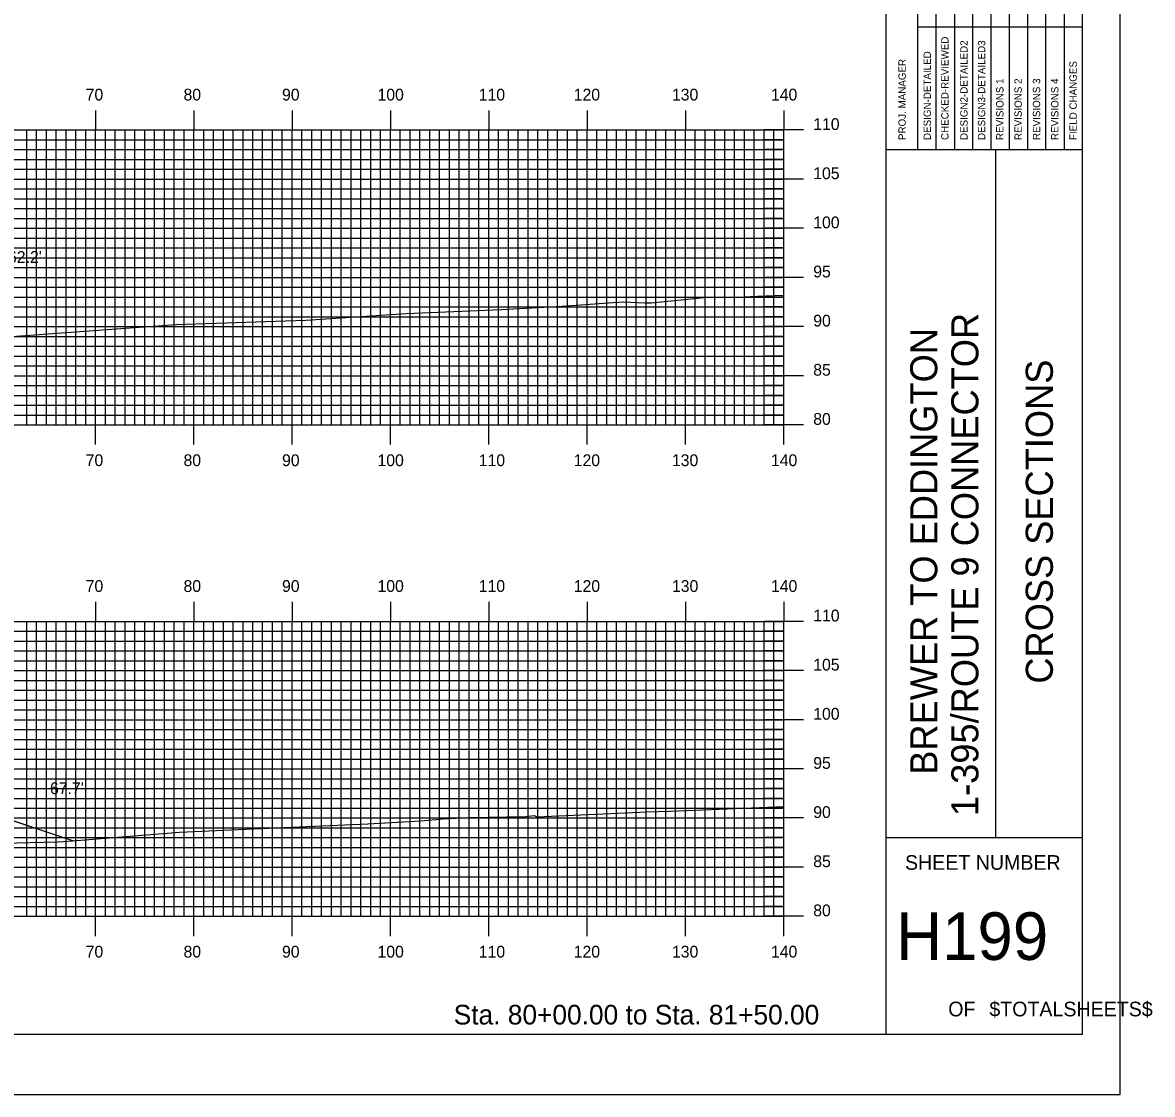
# Model space of a CAD drawing. Extents: x 1762578 to 1762921, y 442591 to 442811.
# Drawn here: x 1762806.4 to 1762921.3, y 442590.5 to 442699.6 of the extents above; entities that cross this region are included whole.
import ezdxf

# ---------------------------------------------------------------- set-up
doc = ezdxf.new("R2010")
doc.units = 0
for name, color, linetype in [('BORDER', 7, 'Continuous'), ('D_Roadway_Centerline', 7, 'Continuous'), ('D_Roadway_SlopeLines', 7, 'Continuous'), ('D_Text_Standard', 7, 'Continuous'), ('H_V ANNOTATION', 7, 'Continuous'), ('MAJOR', 7, 'Continuous'), ('MINOR', 7, 'Continuous'), ('PLOT BOUNDARY', 7, 'Continuous'), ('S_Roadway_Centerline', 7, 'Continuous')]:
    doc.layers.add(name, color=color, linetype=linetype)

msp = doc.modelspace()

# ---------------------------------------------------------------- linework, layer by layer
at = {"layer": 'BORDER'}
for p, q in [((1762894.18, 442596.67), (1762894.18, 442806.67)), ((1762894.18, 442686.67), (1762914.18, 442686.67)), ((1762905.36, 442616.67), (1762905.36, 442686.67)), ((1762894.18, 442616.67), (1762914.18, 442616.67))]:
    msp.add_line(p, q, dxfattribs=at)
msp.add_lwpolyline([(1762594.18, 442596.67), (1762914.18, 442596.67), (1762914.18, 442806.67), (1762594.18, 442806.67)], close=True, dxfattribs=at)
for points in [[(1762899.27, 442686.68), (1762899.27, 442721.67)], [(1762901.14, 442721.67), (1762901.14, 442686.68)], [(1762903, 442686.68), (1762903, 442721.67)], [(1762904.86, 442686.68), (1762904.86, 442721.67)], [(1762906.73, 442686.68), (1762906.73, 442721.67)], [(1762908.59, 442686.68), (1762908.59, 442721.67)], [(1762910.45, 442686.68), (1762910.45, 442721.67)], [(1762912.32, 442686.68), (1762912.32, 442721.67)], [(1762897.41, 442686.68), (1762897.41, 442720.26)], [(1762897.41, 442699.17), (1762914.18, 442699.17)]]:
    msp.add_lwpolyline(points, dxfattribs=at)
at = {"layer": 'D_Roadway_Centerline'}
msp.add_lwpolyline([(1762668.07, 442614.67), (1762668.08, 442614.67), (1762705.54, 442627.15), (1762706.12, 442627.3), (1762706.12, 442627.3), (1762717.54, 442630.15), (1762717.54, 442630.15), (1762726.98, 442630.53), (1762731.78, 442630.72), (1762731.78, 442630.72), (1762738.78, 442630.98), (1762743.78, 442631.16), (1762743.78, 442631.16), (1762750.76, 442631.41), (1762755.78, 442631.59), (1762755.78, 442631.59), (1762763.78, 442631.27), (1762773.95, 442628.72), (1762773.95, 442628.72), (1762774.91, 442628.48), (1762775.78, 442628.27), (1762802.49, 442619.36), (1762811.53, 442616.35)], dxfattribs=at)
at = {"layer": 'D_Roadway_SlopeLines'}
msp.add_lwpolyline([(1762763.78, 442631.27), (1762775.78, 442628.27), (1762811.53, 442616.35)], dxfattribs=at)
at = {"layer": 'MAJOR'}
for p, q in [((1762813.78, 442690.67), (1762813.78, 442688.67)), ((1762823.78, 442690.67), (1762823.78, 442688.67)), ((1762833.78, 442690.67), (1762833.78, 442688.67)), ((1762843.78, 442690.67), (1762843.78, 442688.67)), ((1762853.78, 442690.67), (1762853.78, 442688.67)), ((1762863.78, 442690.67), (1762863.78, 442688.67)), ((1762873.78, 442690.67), (1762873.78, 442688.67)), ((1762883.78, 442690.67), (1762883.78, 442688.67)), ((1762603.78, 442688.67), (1762883.78, 442688.67)), ((1762603.78, 442688.67), (1762883.78, 442688.67)), ((1762813.78, 442658.67), (1762813.78, 442688.67)), ((1762823.78, 442658.67), (1762823.78, 442688.67)), ((1762833.78, 442658.67), (1762833.78, 442688.67)), ((1762843.78, 442658.67), (1762843.78, 442688.67)), ((1762853.78, 442658.67), (1762853.78, 442688.67)), ((1762863.78, 442658.67), (1762863.78, 442688.67)), ((1762873.78, 442658.67), (1762873.78, 442688.67)), ((1762885.78, 442688.67), (1762881.78, 442688.67)), ((1762883.78, 442658.67), (1762883.78, 442688.67)), ((1762883.78, 442658.67), (1762883.78, 442688.67)), ((1762603.78, 442683.67), (1762883.78, 442683.67)), ((1762885.78, 442683.67), (1762881.78, 442683.67)), ((1762603.78, 442678.67), (1762883.78, 442678.67)), ((1762885.78, 442678.67), (1762881.78, 442678.67)), ((1762603.78, 442673.67), (1762883.78, 442673.67)), ((1762885.78, 442673.67), (1762881.78, 442673.67)), ((1762603.78, 442668.67), (1762883.78, 442668.67)), ((1762885.78, 442668.67), (1762881.78, 442668.67)), ((1762603.78, 442663.67), (1762883.78, 442663.67)), ((1762885.78, 442663.67), (1762881.78, 442663.67)), ((1762603.78, 442658.67), (1762883.78, 442658.67)), ((1762603.78, 442658.67), (1762883.78, 442658.67)), ((1762813.78, 442656.66), (1762813.78, 442658.67)), ((1762823.78, 442656.66), (1762823.78, 442658.67)), ((1762833.78, 442656.66), (1762833.78, 442658.67)), ((1762843.78, 442656.66), (1762843.78, 442658.67)), ((1762853.78, 442656.66), (1762853.78, 442658.67)), ((1762863.78, 442656.66), (1762863.78, 442658.67)), ((1762873.78, 442656.66), (1762873.78, 442658.67)), ((1762885.78, 442658.67), (1762881.78, 442658.67)), ((1762883.78, 442656.66), (1762883.78, 442658.67)), ((1762813.78, 442640.67), (1762813.78, 442638.67)), ((1762823.78, 442640.67), (1762823.78, 442638.67)), ((1762833.78, 442640.67), (1762833.78, 442638.67)), ((1762843.78, 442640.67), (1762843.78, 442638.67)), ((1762853.78, 442640.67), (1762853.78, 442638.67)), ((1762863.78, 442640.67), (1762863.78, 442638.67)), ((1762873.78, 442640.67), (1762873.78, 442638.67)), ((1762883.78, 442640.67), (1762883.78, 442638.67)), ((1762603.78, 442638.67), (1762883.78, 442638.67)), ((1762603.78, 442638.67), (1762883.78, 442638.67)), ((1762813.78, 442608.67), (1762813.78, 442638.67)), ((1762823.78, 442608.67), (1762823.78, 442638.67)), ((1762833.78, 442608.67), (1762833.78, 442638.67)), ((1762843.78, 442608.67), (1762843.78, 442638.67)), ((1762853.78, 442608.67), (1762853.78, 442638.67)), ((1762863.78, 442608.67), (1762863.78, 442638.67)), ((1762873.78, 442608.67), (1762873.78, 442638.67)), ((1762885.78, 442638.67), (1762881.78, 442638.67)), ((1762883.78, 442608.67), (1762883.78, 442638.67)), ((1762883.78, 442608.67), (1762883.78, 442638.67)), ((1762603.78, 442633.67), (1762883.78, 442633.67)), ((1762885.78, 442633.67), (1762881.78, 442633.67)), ((1762603.78, 442628.67), (1762883.78, 442628.67)), ((1762885.78, 442628.67), (1762881.78, 442628.67)), ((1762603.78, 442623.67), (1762883.78, 442623.67)), ((1762885.78, 442623.67), (1762881.78, 442623.67)), ((1762603.78, 442618.67), (1762883.78, 442618.67)), ((1762885.78, 442618.67), (1762881.78, 442618.67)), ((1762603.78, 442613.67), (1762883.78, 442613.67)), ((1762885.78, 442613.67), (1762881.78, 442613.67)), ((1762603.78, 442608.67), (1762883.78, 442608.67)), ((1762603.78, 442608.67), (1762883.78, 442608.67)), ((1762813.78, 442606.66), (1762813.78, 442608.67)), ((1762823.78, 442606.66), (1762823.78, 442608.67)), ((1762833.78, 442606.66), (1762833.78, 442608.67)), ((1762843.78, 442606.66), (1762843.78, 442608.67)), ((1762853.78, 442606.66), (1762853.78, 442608.67)), ((1762863.78, 442606.66), (1762863.78, 442608.67)), ((1762873.78, 442606.66), (1762873.78, 442608.67)), ((1762885.78, 442608.67), (1762881.78, 442608.67)), ((1762883.78, 442606.66), (1762883.78, 442608.67))]:
    msp.add_line(p, q, dxfattribs=at)
at = {"layer": 'MINOR'}
for p, q in [((1762806.78, 442658.67), (1762806.78, 442688.67)), ((1762807.78, 442658.67), (1762807.78, 442688.67)), ((1762808.78, 442658.67), (1762808.78, 442688.67)), ((1762809.78, 442658.67), (1762809.78, 442688.67)), ((1762810.78, 442658.67), (1762810.78, 442688.67)), ((1762811.78, 442658.67), (1762811.78, 442688.67)), ((1762812.78, 442658.67), (1762812.78, 442688.67)), ((1762814.78, 442658.67), (1762814.78, 442688.67)), ((1762815.78, 442658.67), (1762815.78, 442688.67)), ((1762816.78, 442658.67), (1762816.78, 442688.67)), ((1762817.78, 442658.67), (1762817.78, 442688.67)), ((1762818.78, 442658.67), (1762818.78, 442688.67)), ((1762819.78, 442658.67), (1762819.78, 442688.67)), ((1762820.78, 442658.67), (1762820.78, 442688.67)), ((1762821.78, 442658.67), (1762821.78, 442688.67)), ((1762822.78, 442658.67), (1762822.78, 442688.67)), ((1762824.78, 442658.67), (1762824.78, 442688.67)), ((1762825.78, 442658.67), (1762825.78, 442688.67)), ((1762826.78, 442658.67), (1762826.78, 442688.67)), ((1762827.78, 442658.67), (1762827.78, 442688.67)), ((1762828.78, 442658.67), (1762828.78, 442688.67)), ((1762829.78, 442658.67), (1762829.78, 442688.67)), ((1762830.78, 442658.67), (1762830.78, 442688.67)), ((1762831.78, 442658.67), (1762831.78, 442688.67)), ((1762832.78, 442658.67), (1762832.78, 442688.67)), ((1762834.78, 442658.67), (1762834.78, 442688.67)), ((1762835.78, 442658.67), (1762835.78, 442688.67)), ((1762836.78, 442658.67), (1762836.78, 442688.67)), ((1762837.78, 442658.67), (1762837.78, 442688.67)), ((1762838.78, 442658.67), (1762838.78, 442688.67)), ((1762839.78, 442658.67), (1762839.78, 442688.67)), ((1762840.78, 442658.67), (1762840.78, 442688.67)), ((1762841.78, 442658.67), (1762841.78, 442688.67)), ((1762842.78, 442658.67), (1762842.78, 442688.67)), ((1762844.78, 442658.67), (1762844.78, 442688.67)), ((1762845.78, 442658.67), (1762845.78, 442688.67)), ((1762846.78, 442658.67), (1762846.78, 442688.67)), ((1762847.78, 442658.67), (1762847.78, 442688.67)), ((1762848.78, 442658.67), (1762848.78, 442688.67)), ((1762849.78, 442658.67), (1762849.78, 442688.67)), ((1762850.78, 442658.67), (1762850.78, 442688.67)), ((1762851.78, 442658.67), (1762851.78, 442688.67)), ((1762852.78, 442658.67), (1762852.78, 442688.67)), ((1762854.78, 442658.67), (1762854.78, 442688.67)), ((1762855.78, 442658.67), (1762855.78, 442688.67)), ((1762856.78, 442658.67), (1762856.78, 442688.67)), ((1762857.78, 442658.67), (1762857.78, 442688.67)), ((1762858.78, 442658.67), (1762858.78, 442688.67)), ((1762859.78, 442658.67), (1762859.78, 442688.67)), ((1762860.78, 442658.67), (1762860.78, 442688.67)), ((1762861.78, 442658.67), (1762861.78, 442688.67)), ((1762862.78, 442658.67), (1762862.78, 442688.67)), ((1762864.78, 442658.67), (1762864.78, 442688.67)), ((1762865.78, 442658.67), (1762865.78, 442688.67)), ((1762866.78, 442658.67), (1762866.78, 442688.67)), ((1762867.78, 442658.67), (1762867.78, 442688.67)), ((1762868.78, 442658.67), (1762868.78, 442688.67)), ((1762869.78, 442658.67), (1762869.78, 442688.67)), ((1762870.78, 442658.67), (1762870.78, 442688.67)), ((1762871.78, 442658.67), (1762871.78, 442688.67)), ((1762872.78, 442658.67), (1762872.78, 442688.67)), ((1762874.78, 442658.67), (1762874.78, 442688.67)), ((1762875.78, 442658.67), (1762875.78, 442688.67)), ((1762876.78, 442658.67), (1762876.78, 442688.67)), ((1762877.78, 442658.67), (1762877.78, 442688.67)), ((1762878.78, 442658.67), (1762878.78, 442688.67)), ((1762879.78, 442658.67), (1762879.78, 442688.67)), ((1762880.78, 442658.67), (1762880.78, 442688.67)), ((1762881.78, 442658.67), (1762881.78, 442688.67)), ((1762882.78, 442658.67), (1762882.78, 442688.67)), ((1762603.78, 442687.67), (1762883.78, 442687.67)), ((1762883.78, 442687.67), (1762881.78, 442687.67)), ((1762603.78, 442686.67), (1762883.78, 442686.67)), ((1762883.78, 442686.67), (1762881.78, 442686.67)), ((1762603.78, 442685.67), (1762883.78, 442685.67)), ((1762883.78, 442685.67), (1762881.78, 442685.67)), ((1762603.78, 442684.67), (1762883.78, 442684.67)), ((1762883.78, 442684.67), (1762881.78, 442684.67)), ((1762603.78, 442682.67), (1762883.78, 442682.67)), ((1762883.78, 442682.67), (1762881.78, 442682.67)), ((1762603.78, 442681.67), (1762883.78, 442681.67)), ((1762883.78, 442681.67), (1762881.78, 442681.67)), ((1762603.78, 442680.67), (1762883.78, 442680.67)), ((1762883.78, 442680.67), (1762881.78, 442680.67)), ((1762603.78, 442679.67), (1762883.78, 442679.67)), ((1762883.78, 442679.67), (1762881.78, 442679.67)), ((1762603.78, 442677.67), (1762883.78, 442677.67)), ((1762883.78, 442677.67), (1762881.78, 442677.67)), ((1762603.78, 442676.67), (1762883.78, 442676.67)), ((1762883.78, 442676.67), (1762881.78, 442676.67)), ((1762603.78, 442675.67), (1762883.78, 442675.67)), ((1762603.78, 442674.67), (1762883.78, 442674.67)), ((1762883.78, 442675.67), (1762881.78, 442675.67)), ((1762883.78, 442674.67), (1762881.78, 442674.67)), ((1762603.78, 442672.67), (1762883.78, 442672.67)), ((1762883.78, 442672.67), (1762881.78, 442672.67)), ((1762603.78, 442671.67), (1762883.78, 442671.67)), ((1762883.78, 442671.67), (1762881.78, 442671.67)), ((1762603.78, 442670.67), (1762883.78, 442670.67)), ((1762883.78, 442670.67), (1762881.78, 442670.67)), ((1762603.78, 442669.67), (1762883.78, 442669.67)), ((1762883.78, 442669.67), (1762881.78, 442669.67)), ((1762603.78, 442667.67), (1762883.78, 442667.67)), ((1762603.78, 442666.67), (1762883.78, 442666.67)), ((1762883.78, 442667.67), (1762881.78, 442667.67)), ((1762883.78, 442666.67), (1762881.78, 442666.67)), ((1762603.78, 442665.67), (1762883.78, 442665.67)), ((1762883.78, 442665.67), (1762881.78, 442665.67)), ((1762603.78, 442664.67), (1762883.78, 442664.67)), ((1762883.78, 442664.67), (1762881.78, 442664.67)), ((1762603.78, 442662.67), (1762883.78, 442662.67)), ((1762883.78, 442662.67), (1762881.78, 442662.67)), ((1762603.78, 442661.67), (1762883.78, 442661.67)), ((1762883.78, 442661.67), (1762881.78, 442661.67)), ((1762603.78, 442660.67), (1762883.78, 442660.67)), ((1762603.78, 442659.67), (1762883.78, 442659.67)), ((1762883.78, 442660.67), (1762881.78, 442660.67)), ((1762883.78, 442659.67), (1762881.78, 442659.67)), ((1762806.78, 442608.67), (1762806.78, 442638.67)), ((1762807.78, 442608.67), (1762807.78, 442638.67)), ((1762808.78, 442608.67), (1762808.78, 442638.67)), ((1762809.78, 442608.67), (1762809.78, 442638.67)), ((1762810.78, 442608.67), (1762810.78, 442638.67)), ((1762811.78, 442608.67), (1762811.78, 442638.67)), ((1762812.78, 442608.67), (1762812.78, 442638.67)), ((1762814.78, 442608.67), (1762814.78, 442638.67)), ((1762815.78, 442608.67), (1762815.78, 442638.67)), ((1762816.78, 442608.67), (1762816.78, 442638.67)), ((1762817.78, 442608.67), (1762817.78, 442638.67)), ((1762818.78, 442608.67), (1762818.78, 442638.67)), ((1762819.78, 442608.67), (1762819.78, 442638.67)), ((1762820.78, 442608.67), (1762820.78, 442638.67)), ((1762821.78, 442608.67), (1762821.78, 442638.67)), ((1762822.78, 442608.67), (1762822.78, 442638.67)), ((1762824.78, 442608.67), (1762824.78, 442638.67)), ((1762825.78, 442608.67), (1762825.78, 442638.67)), ((1762826.78, 442608.67), (1762826.78, 442638.67)), ((1762827.78, 442608.67), (1762827.78, 442638.67)), ((1762828.78, 442608.67), (1762828.78, 442638.67)), ((1762829.78, 442608.67), (1762829.78, 442638.67)), ((1762830.78, 442608.67), (1762830.78, 442638.67)), ((1762831.78, 442608.67), (1762831.78, 442638.67)), ((1762832.78, 442608.67), (1762832.78, 442638.67)), ((1762834.78, 442608.67), (1762834.78, 442638.67)), ((1762835.78, 442608.67), (1762835.78, 442638.67)), ((1762836.78, 442608.67), (1762836.78, 442638.67)), ((1762837.78, 442608.67), (1762837.78, 442638.67)), ((1762838.78, 442608.67), (1762838.78, 442638.67)), ((1762839.78, 442608.67), (1762839.78, 442638.67)), ((1762840.78, 442608.67), (1762840.78, 442638.67)), ((1762841.78, 442608.67), (1762841.78, 442638.67)), ((1762842.78, 442608.67), (1762842.78, 442638.67)), ((1762844.78, 442608.67), (1762844.78, 442638.67)), ((1762845.78, 442608.67), (1762845.78, 442638.67)), ((1762846.78, 442608.67), (1762846.78, 442638.67)), ((1762847.78, 442608.67), (1762847.78, 442638.67)), ((1762848.78, 442608.67), (1762848.78, 442638.67)), ((1762849.78, 442608.67), (1762849.78, 442638.67)), ((1762850.78, 442608.67), (1762850.78, 442638.67)), ((1762851.78, 442608.67), (1762851.78, 442638.67)), ((1762852.78, 442608.67), (1762852.78, 442638.67)), ((1762854.78, 442608.67), (1762854.78, 442638.67)), ((1762855.78, 442608.67), (1762855.78, 442638.67)), ((1762856.78, 442608.67), (1762856.78, 442638.67)), ((1762857.78, 442608.67), (1762857.78, 442638.67)), ((1762858.78, 442608.67), (1762858.78, 442638.67)), ((1762859.78, 442608.67), (1762859.78, 442638.67)), ((1762860.78, 442608.67), (1762860.78, 442638.67)), ((1762861.78, 442608.67), (1762861.78, 442638.67)), ((1762862.78, 442608.67), (1762862.78, 442638.67)), ((1762864.78, 442608.67), (1762864.78, 442638.67)), ((1762865.78, 442608.67), (1762865.78, 442638.67)), ((1762866.78, 442608.67), (1762866.78, 442638.67)), ((1762867.78, 442608.67), (1762867.78, 442638.67)), ((1762868.78, 442608.67), (1762868.78, 442638.67)), ((1762869.78, 442608.67), (1762869.78, 442638.67)), ((1762870.78, 442608.67), (1762870.78, 442638.67)), ((1762871.78, 442608.67), (1762871.78, 442638.67)), ((1762872.78, 442608.67), (1762872.78, 442638.67)), ((1762874.78, 442608.67), (1762874.78, 442638.67)), ((1762875.78, 442608.67), (1762875.78, 442638.67)), ((1762876.78, 442608.67), (1762876.78, 442638.67)), ((1762877.78, 442608.67), (1762877.78, 442638.67)), ((1762878.78, 442608.67), (1762878.78, 442638.67)), ((1762879.78, 442608.67), (1762879.78, 442638.67)), ((1762880.78, 442608.67), (1762880.78, 442638.67)), ((1762881.78, 442608.67), (1762881.78, 442638.67)), ((1762882.78, 442608.67), (1762882.78, 442638.67)), ((1762603.78, 442637.67), (1762883.78, 442637.67)), ((1762603.78, 442636.67), (1762883.78, 442636.67)), ((1762883.78, 442637.67), (1762881.78, 442637.67)), ((1762883.78, 442636.67), (1762881.78, 442636.67)), ((1762603.78, 442635.67), (1762883.78, 442635.67)), ((1762883.78, 442635.67), (1762881.78, 442635.67)), ((1762603.78, 442634.67), (1762883.78, 442634.67)), ((1762883.78, 442634.67), (1762881.78, 442634.67)), ((1762603.78, 442632.67), (1762883.78, 442632.67)), ((1762883.78, 442632.67), (1762881.78, 442632.67)), ((1762603.78, 442631.67), (1762883.78, 442631.67)), ((1762883.78, 442631.67), (1762881.78, 442631.67)), ((1762603.78, 442630.67), (1762883.78, 442630.67)), ((1762883.78, 442630.67), (1762881.78, 442630.67)), ((1762603.78, 442629.67), (1762883.78, 442629.67)), ((1762883.78, 442629.67), (1762881.78, 442629.67)), ((1762603.78, 442627.67), (1762883.78, 442627.67)), ((1762883.78, 442627.67), (1762881.78, 442627.67)), ((1762603.78, 442626.67), (1762883.78, 442626.67)), ((1762883.78, 442626.67), (1762881.78, 442626.67)), ((1762603.78, 442625.67), (1762883.78, 442625.67)), ((1762883.78, 442625.67), (1762881.78, 442625.67)), ((1762603.78, 442624.67), (1762883.78, 442624.67)), ((1762883.78, 442624.67), (1762881.78, 442624.67)), ((1762603.78, 442622.67), (1762883.78, 442622.67)), ((1762883.78, 442622.67), (1762881.78, 442622.67)), ((1762603.78, 442621.67), (1762883.78, 442621.67)), ((1762603.78, 442620.67), (1762883.78, 442620.67)), ((1762883.78, 442621.67), (1762881.78, 442621.67)), ((1762883.78, 442620.67), (1762881.78, 442620.67)), ((1762603.78, 442619.67), (1762883.78, 442619.67)), ((1762883.78, 442619.67), (1762881.78, 442619.67)), ((1762603.78, 442617.67), (1762883.78, 442617.67)), ((1762883.78, 442617.67), (1762881.78, 442617.67)), ((1762603.78, 442616.67), (1762883.78, 442616.67)), ((1762883.78, 442616.67), (1762881.78, 442616.67)), ((1762603.78, 442615.67), (1762883.78, 442615.67)), ((1762883.78, 442615.67), (1762881.78, 442615.67)), ((1762603.78, 442614.67), (1762883.78, 442614.67)), ((1762883.78, 442614.67), (1762881.78, 442614.67)), ((1762603.78, 442612.67), (1762883.78, 442612.67)), ((1762883.78, 442612.67), (1762881.78, 442612.67)), ((1762603.78, 442611.67), (1762883.78, 442611.67)), ((1762883.78, 442611.67), (1762881.78, 442611.67)), ((1762603.78, 442610.67), (1762883.78, 442610.67)), ((1762883.78, 442610.67), (1762881.78, 442610.67)), ((1762603.78, 442609.67), (1762883.78, 442609.67)), ((1762883.78, 442609.67), (1762881.78, 442609.67))]:
    msp.add_line(p, q, dxfattribs=at)
at = {"layer": 'PLOT BOUNDARY'}
msp.add_lwpolyline([(1762577.99, 442590.55), (1762917.99, 442590.55), (1762917.99, 442810.55), (1762577.99, 442810.55)], close=True, dxfattribs=at)
at = {"layer": 'S_Roadway_Centerline'}
for points in [[(1762800.16, 442667.29), (1762816.36, 442668.47), (1762821.98, 442668.87), (1762835.18, 442669.31), (1762845.38, 442669.99), (1762855.08, 442670.39), (1762861.24, 442670.74), (1762866.42, 442671.11), (1762867.45, 442671.17), (1762869.66, 442671.07), (1762870.28, 442671.08), (1762876, 442671.65), (1762878.35, 442671.64), (1762881.09, 442671.76), (1762883.78, 442671.87)], [(1762798.83, 442615.96), (1762809.91, 442616.24), (1762810.51, 442616.27), (1762811.44, 442616.34), (1762822.31, 442617.22), (1762829.06, 442617.52), (1762841.49, 442618.08), (1762846.87, 442618.37), (1762849.13, 442618.58), (1762851.79, 442618.71), (1762857.54, 442618.82), (1762858.4, 442618.93), (1762858.68, 442618.78), (1762869.15, 442619.27), (1762869.75, 442619.29), (1762872.27, 442619.36), (1762883.78, 442619.83)]]:
    msp.add_lwpolyline(points, dxfattribs=at)

# ---------------------------------------------------------------- texts
at = {"layer": 'BORDER'}
for s, height, p in [('CHECKED-REVIEWED', 0.7455, (1762900.54, 442687.65)), ('DESIGN2-DETAILED2', 0.7455, (1762902.48, 442687.65)), ('DESIGN3-DETAILED3', 0.7455, (1762904.27, 442687.65)), ('DESIGN-DETAILED', 0.7455, (1762898.75, 442687.65)), ('PROJ. MANAGER', 0.7455, (1762896.19, 442687.65)), ('FIELD CHANGES', 0.7455, (1762913.58, 442687.65)), ('REVISIONS 1', 0.7455, (1762906.13, 442687.65)), ('REVISIONS 2', 0.7455, (1762907.99, 442687.65)), ('REVISIONS 3', 0.7455, (1762909.86, 442687.65)), ('REVISIONS 4', 0.7455, (1762911.72, 442687.65)), ('1-395/ROUTE 9 CONNECTOR', 2.7557, (1762903.58, 442618.87)), ('BREWER TO EDDINGTON', 2.7557, (1762899.4, 442623.07)), ('CROSS SECTIONS', 2.7557, (1762911.15, 442632.34))]:
    msp.add_text(s, height=height, rotation=90, dxfattribs=at).set_placement(p)
for s, height, p in [('SHEET NUMBER', 1.4905, (1762896.11, 442613.4)), ('H199', 4.839, (1762895.21, 442604.23)), ('OF', 1.491, (1762900.51, 442598.49)), ('$TOTALSHEETS$', 1.4905, (1762904.69, 442598.49))]:
    msp.add_text(s, height=height, dxfattribs=at).set_placement(p)
at = {"layer": 'D_Text_Standard'}
for s, p in [("62.2'", (1762804.88, 442675.15)), ("67.7'", (1762809.15, 442621.1))]:
    msp.add_text(s, height=1.2, dxfattribs=at).set_placement(p)
at = {"layer": 'H_V ANNOTATION'}
for s, height, p in [('70', 1.2, (1762812.78, 442691.67)), ('80', 1.2, (1762822.73, 442691.67)), ('90', 1.2, (1762832.75, 442691.67)), ('100', 1.2, (1762842.46, 442691.67)), ('110', 1.2, (1762852.76, 442691.67)), ('120', 1.2, (1762862.42, 442691.67)), ('130', 1.2, (1762872.41, 442691.67)), ('140', 1.2, (1762882.48, 442691.67)), ('110', 1.2, (1762886.78, 442688.67)), ('105', 1.2, (1762886.78, 442683.67)), ('100', 1.2, (1762886.78, 442678.67)), ('95', 1.2, (1762886.78, 442673.67)), ('90', 1.2, (1762886.78, 442668.67)), ('85', 1.2, (1762886.78, 442663.67)), ('80', 1.2, (1762886.78, 442658.67)), ('70', 1.2, (1762812.78, 442654.47)), ('80', 1.2, (1762822.73, 442654.47)), ('90', 1.2, (1762832.75, 442654.47)), ('100', 1.2, (1762842.46, 442654.47)), ('110', 1.2, (1762852.76, 442654.47)), ('120', 1.2, (1762862.42, 442654.47)), ('130', 1.2, (1762872.41, 442654.47)), ('140', 1.2, (1762882.48, 442654.47)), ('70', 1.2, (1762812.78, 442641.67)), ('80', 1.2, (1762822.73, 442641.67)), ('90', 1.2, (1762832.75, 442641.67)), ('100', 1.2, (1762842.46, 442641.67)), ('110', 1.2, (1762852.76, 442641.67)), ('120', 1.2, (1762862.42, 442641.67)), ('130', 1.2, (1762872.41, 442641.67)), ('140', 1.2, (1762882.48, 442641.67)), ('110', 1.2, (1762886.78, 442638.67)), ('105', 1.2, (1762886.78, 442633.67)), ('100', 1.2, (1762886.78, 442628.67)), ('95', 1.2, (1762886.78, 442623.67)), ('90', 1.2, (1762886.78, 442618.67)), ('85', 1.2, (1762886.78, 442613.67)), ('80', 1.2, (1762886.78, 442608.67)), ('70', 1.2, (1762812.78, 442604.47)), ('80', 1.2, (1762822.73, 442604.47)), ('90', 1.2, (1762832.75, 442604.47)), ('100', 1.2, (1762842.46, 442604.47)), ('110', 1.2, (1762852.76, 442604.47)), ('120', 1.2, (1762862.42, 442604.47)), ('130', 1.2, (1762872.41, 442604.47)), ('140', 1.2, (1762882.48, 442604.47)), ('Sta. 80+00.00 to Sta. 81+50.00', 2.0004, (1762850.21, 442597.66))]:
    msp.add_text(s, height=height, dxfattribs=at).set_placement(p)

doc.saveas('drawing.dxf')
